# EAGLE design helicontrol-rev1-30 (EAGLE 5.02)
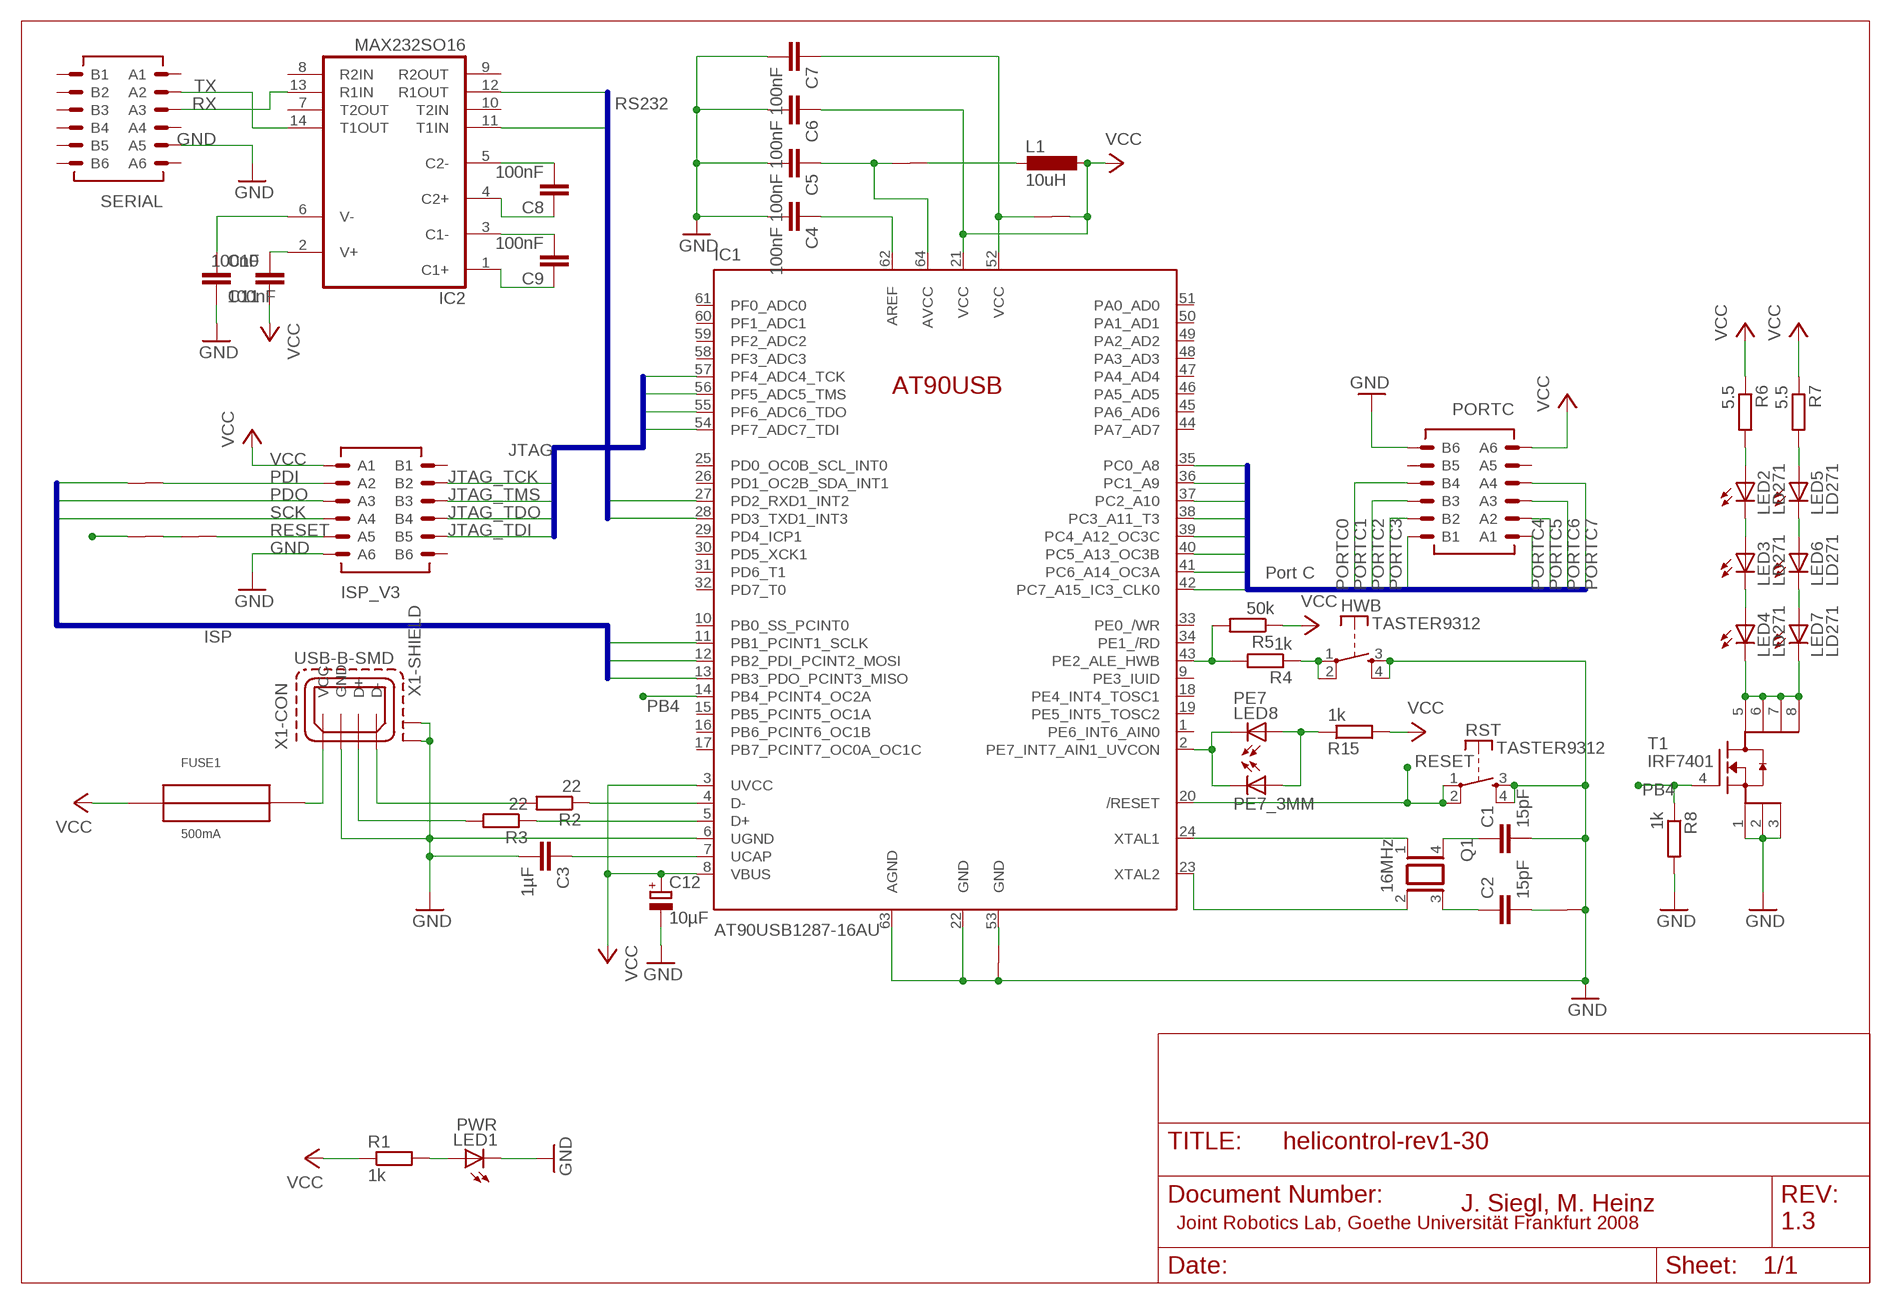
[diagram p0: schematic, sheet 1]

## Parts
C1  15pF  C-EUC1206  [C1206]
C2  15pF  C-EUC1206  [C1206]
C3  1µF  C-EUC1206  [C1206]
C4  100nF  C-EUC1206  [C1206]
C5  100nF  C-EUC1206  [C1206]
C6  100nF  C-EUC1206  [C1206]
C7  100nF  C-EUC1206  [C1206]
C8  100nF  C-EUC1206  [C1206]
C9  100nF  C-EUC1206  [C1206]
C10  100nF  C-EUC1206  [C1206]
C11  100nF  C-EUC1206  [C1206]
C12  10µF  CPOL-EUUD-5X5,8  [UD-5X5,8_NICHICON]
FUSE1  500mA  SMD-FUSE  [SMD-FUSE]
HWB  TASTER9312  [TASTER9312]
IC1  AT90USB1287-16AU  AT90USB-TQFP  [TQFP64]
IC2  MAX232SO16  [SO16]
ISP_V3  ML12G  [ML12G]
J0  R01206W  [R1206W]
J1  R01206W  [R1206W]
J2  R01206W  [R1206W]
J3  R01206W  [R1206W]
J4  R01206W  [R1206W]
J5  R01206W  [R1206W]
J6  R01206W  [R1206W]
L1  10uH  L-EUL2012C  [L2012C]
LED1  PWR  LEDCHIPLED_1206  [CHIPLED_1206]
LED2  LD271  LED5MM  [LED5MM]
LED3  LD271  LED5MM  [LED5MM]
LED4  LD271  LED5MM  [LED5MM]
LED5  LD271  LED5MM  [LED5MM]
LED6  LD271  LED5MM  [LED5MM]
LED7  LD271  LED5MM  [LED5MM]
LED8  PE7  LEDCHIPLED_1206  [CHIPLED_1206]
PE7_3MM  LED3MM  [LED3MM]
PORTC  ML12G  [ML12G]
Q1  16MHz  XTAL4-SMD  [XTAL4]
R1  1k  R-EU_R1206W  [R1206W]
R2  22  R-EU_R1206W  [R1206W]
R3  22  R-EU_R1206W  [R1206W]
R4  1k  R-EU_R1206W  [R1206W]
R5  50k  R-EU_R1206W  [R1206W]
R6  5.5  R-EU_R1206W  [R1206W]
R7  5.5  R-EU_R1206W  [R1206W]
R8  1k  R-EU_R1206W  [R1206W]
R15  1k  R-EU_R1206W  [R1206W]
RST  TASTER9312  [TASTER9312]
SERIAL  ML12G  [ML12G]
T1  IRF7401  [SO8]
X1  USB-B-SMD  [USB-B-SMD]

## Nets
D+: R3.2 X1.D+(-CON:D+)
D-: R2.2 X1.D-(-CON:D-)
GND: C1.2 C2.2 C3.2 C4.2 C5.2 C6.2 C7.2 C10.2 C12.- HWB.3(S) HWB.4(S) IC1.6(UGND) IC1.22(GND) IC1.53(GND) IC1.63(AGND) ISP_V3.A6 J0.1 J0.2 J1.1 J1.2 LED1.C PORTC.B6 R8.2 RST.3(S) RST.4(S) SERIAL.A5 T1.1(S) T1.2(S) T1.3(S) X1.GND(-CON:GND) X1.M1(-SHIELD:S1) X1.M2(-SHIELD:S2)
JTAG_TCK: IC1.57(PF4_ADC4_TCK) ISP_V3.B2
JTAG_TDI: IC1.54(PF7_ADC7_TDI) ISP_V3.B5
JTAG_TDO: IC1.55(PF6_ADC6_TDO) ISP_V3.B4
JTAG_TMS: IC1.56(PF5_ADC5_TMS) ISP_V3.B3
N$1: FUSE1.P$2 X1.VCC(-CON:VCC)
N$2: LED1.A R1.2
N$3: IC1.23(XTAL2) Q1.2
N$4: IC1.24(XTAL1) Q1.1
N$5: IC1.43(PE2_ALE_HWB) R4.2 R5.2
N$6: C4.1 IC1.62(AREF)
N$9: IC1.4(D-) R2.1
N$10: IC1.5(D+) R3.1
N$11: LED2.A R6.2
N$12: C5.1 IC1.64(AVCC) J2.1 J2.2 L1.2
N$13: C3.1 IC1.7(UCAP)
N$14: LED2.K(C) LED3.A
N$15: HWB.1(P) HWB.2(P) R4.1
N$16: LED3.K(C) LED4.A
N$17: C8.1 IC2.4(C2+)
N$18: C8.2 IC2.5(C2-)
N$19: C9.2 IC2.3(C1-)
N$20: C9.1 IC2.1(C1+)
N$21: C10.1 IC2.6(V-)
N$22: C11.2 IC2.2(V+)
N$23: C1.1 Q1.4
N$24: C2.1 Q1.3
N$25: LED4.K(C) LED7.K(C) T1.5(D) T1.6(D) T1.7(D) T1.8(D)
N$26: J4.1 J5.2
N$27: LED6.K(C) LED7.A
N$28: LED5.K(C) LED6.A
N$29: LED5.A R7.2
N$31: ISP_V3.A5 J5.1
N$32: ISP_V3.A2 J6.1
N$35: IC1.2(PE7_INT7_AIN1_UVCON) LED8.C PE7_3MM.K(C)
N$36: LED8.A PE7_3MM.A R15.1
PB4: IC1.14(PB4_PCINT4_OC2A) R8.1 T1.4(G)
PDI: IC1.12(PB2_PDI_PCINT2_MOSI) J6.2
PDO: IC1.13(PB3_PDO_PCINT3_MISO) ISP_V3.A3
PORTC0: IC1.35(PC0_A8) PORTC.B4
PORTC1: IC1.36(PC1_A9) PORTC.B3
PORTC2: IC1.37(PC2_A10) PORTC.B2
PORTC3: IC1.38(PC3_A11_T3) PORTC.B1
PORTC4: IC1.39(PC4_A12_OC3C) PORTC.A1
PORTC5: IC1.40(PC5_A13_OC3B) PORTC.A2
PORTC6: IC1.41(PC6_A14_OC3A) PORTC.A3
PORTC7: IC1.42(PC7_A15_IC3_CLK0) PORTC.A4
RESET: IC1.20(/RESET) J4.2 RST.1(P) RST.2(P)
RX: IC2.13(R1IN) SERIAL.A3
RXOUT: IC1.27(PD2_RXD1_INT2) IC2.12(R1OUT)
SCK: IC1.11(PB1_PCINT1_SCLK) ISP_V3.A4
TX: IC2.14(T1OUT) SERIAL.A2
TXIN: IC1.28(PD3_TXD1_INT3) IC2.11(T1IN)
VCC: C6.1 C7.1 C11.1 C12.+ FUSE1.P$1 IC1.3(UVCC) IC1.8(VBUS) IC1.21(VCC) IC1.52(VCC) ISP_V3.A1 J3.1 J3.2 L1.1 PORTC.A6 R1.1 R5.1 R6.1 R7.1 R15.2
Unconnected: IC1.1(PE6_INT6_AIN0) IC1.9(PE3_IUID) IC1.10(PB0_SS_PCINT0) IC1.15(PB5_PCINT5_OC1A) IC1.16(PB6_PCINT6_OC1B) IC1.17(PB7_PCINT7_OC0A_OC1C) IC1.18(PE4_INT4_TOSC1) IC1.19(PE5_INT5_TOSC2) IC1.25(PD0_OC0B_SCL_INT0) IC1.26(PD1_OC2B_SDA_INT1) IC1.29(PD4_ICP1) IC1.30(PD5_XCK1) IC1.31(PD6_T1) IC1.32(PD7_T0) IC1.33(PE0_/WR) IC1.34(PE1_/RD) IC1.44(PA7_AD7) IC1.45(PA6_AD6) IC1.46(PA5_AD5) IC1.47(PA4_AD4) IC1.48(PA3_AD3) IC1.49(PA2_AD2) IC1.50(PA1_AD1) IC1.51(PA0_AD0) IC1.58(PF3_ADC3) IC1.59(PF2_ADC2) IC1.60(PF1_ADC1) IC1.61(PF0_ADC0) IC2.7(T2OUT) IC2.8(R2IN) IC2.9(R2OUT) IC2.10(T2IN) ISP_V3.B1 ISP_V3.B6 PORTC.A5 PORTC.B5 SERIAL.A1 SERIAL.A4 SERIAL.A6 SERIAL.B1 SERIAL.B2 SERIAL.B3 SERIAL.B4 SERIAL.B5 SERIAL.B6

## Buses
PDI,PDO,SCK
RXOUT,TXIN
JTAG_TCK,JTAG_TMS,JTAG_TDO,JTAG_TDI
PORTC[0..7]

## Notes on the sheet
- RS232
- JTAG
- Port C
- ISP
- J. Siegl, M. Heinz
- Joint Robotics Lab, Goethe Universität Frankfurt 2008 | 1.3

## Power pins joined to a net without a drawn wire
GND: IC2.15(GND)
VCC: IC2.16(VCC)

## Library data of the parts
C1-C11 = resistor:C-EU: CAPACITOR, European symbol
C12 = rcl:CPOL-EU: POLARIZED CAPACITOR, European symbol
FUSE1 = cvg-smd:SMD-FUSE: SMD-FUSE
HWB RST = cvg-smd:TASTER9312: TASTER 9312 SWITCH Von Reichelt Elektronik
IC1 = controller-micro_atmel_jd:AT90USB
IC2 = cvg-smd:MAX232: RS232 TRANSEIVER
ISP_V3 PORTC SERIAL = cvg-con-erni:ML12G: Male SMC Connector vertical, type Q, low profile
J0 J1-J6 = cvg-smd:R0: Zero Ohm Resistor
L1 = rcl:L-EU: INDUCTOR, European symbol
LED1-LED8 PE7_3MM = led:LED: LED
Q1 = cvg-smd:XTAL4-SMD: xtal
R1-R8 R15 = rcl:R-EU_: RESISTOR, European symbol
T1 = cvg-smd:IRF7401: IRF 7401 n-Channel Hexfet Power Mosfet SO-8
X1 = joergsmikrocontroller-net-usb:USB-B-SMD

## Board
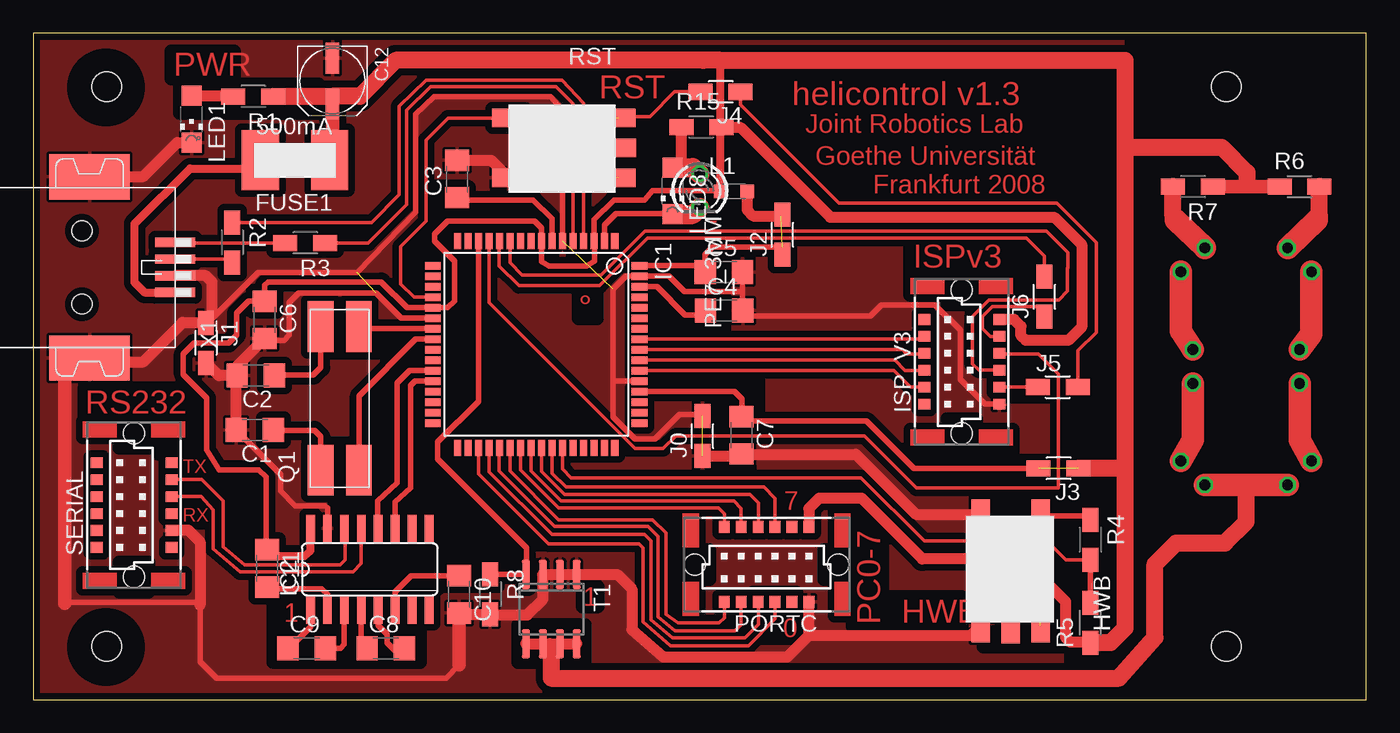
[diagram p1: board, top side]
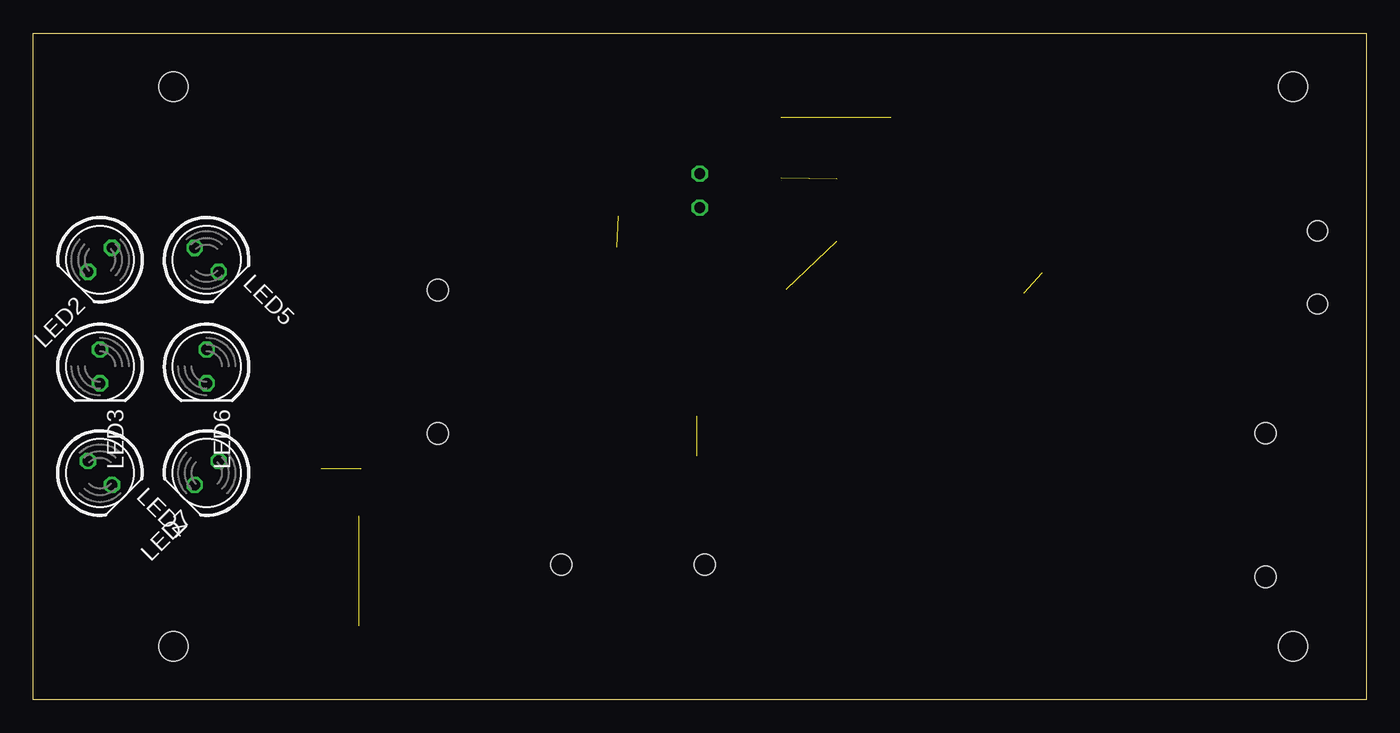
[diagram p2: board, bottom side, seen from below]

Size 100 x 50 mm. Coordinates in mm from the lower left corner, seen from the top.
Outline: 0,50 0,0 100,0 100,50 0,50
Copper layers (1*16): Top 0.035mm / dielectric 1.5mm / Bottom 0.035mm
Design rules "PCB-POOL *": minimum track width 6mil, minimum drill 12mil, track to track 6mil, track to pad 6mil, pad to pad 6mil, via to via 6mil, smd to smd 6mil, copper to edge 20mil, drill to drill 8mil, minimum pad ring 8mil, minimum via ring 6mil, stop-mask expansion 3mil, vias tented up to drill 0mil, thermal gap 8mil
Holes 2.2 mm at 5.5,46 5.5,4 89.5,46 89.5,4
tRestrict: area 3.2,43.8 to 7.7,48.2; area 87.3,1.7 to 91.7,6.1; area 87.2,43.8 to 91.7,48.2; area 3.2,1.8 to 7.7,6.2; area 82.6,49.1 to 83,49.5; area 18,2.8 to 29,7.2; area 29.8,8.1 to 30.6,8.8; area 8.2,31.4 to 9,32.9; area 10.3,46.6 to 15.1,48.6; area 15.4,44.5 to 20.1,46; area 44.2,38 to 47.2,43.4; area 29.8,36.6 to 32.5,38.5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

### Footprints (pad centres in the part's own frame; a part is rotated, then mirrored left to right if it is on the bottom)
C1206 = smd 1.6 x 1.8: 1 -1.4,0; 2 1.4,0
UD-5X5,8_NICHICON = smd 2.3 x 1: + 1.725,0; - -1.7,0
SMD-FUSE = smd 2.794 x 4.5: P$1 -2.591,0; P$2 2.591,0
TASTER9312 = smd 2.5 x 1.4: 1 -7,2.5; 2 1.25,2.5; 3 -7,-2; 4 1.25,-2 | smd 3 x 1.4: 5 1.05,0.25
TQFP64 = smd 1.194 x 0.559: 1 -7.76,5.905; 2 -7.76,5.118; 3 -7.76,4.331; 4 -7.76,3.543; 5 -7.76,2.756; 6 -7.76,1.968; 7 -7.76,1.181; 8 -7.76,0.394; 9 -7.76,-0.394; 10 -7.76,-1.181; 11 -7.76,-1.968; 12 -7.76,-2.756; 13 -7.76,-3.543; 14 -7.76,-4.331; 15 -7.76,-5.118; 16 -7.76,-5.905; 33 7.76,-5.905; 34 7.76,-5.118; 35 7.76,-4.331; 36 7.76,-3.543; 37 7.76,-2.756; 38 7.76,-1.968; 39 7.76,-1.181; 40 7.76,-0.394; 41 7.76,0.394; 42 7.76,1.181; 43 7.76,1.968; 44 7.76,2.756; 45 7.76,3.543; 46 7.76,4.331; 47 7.76,5.118; 48 7.76,5.905 | smd 0.559 x 1.194: 17 -5.905,-7.76; 18 -5.118,-7.76; 19 -4.331,-7.76; 20 -3.543,-7.76; 21 -2.756,-7.76; 22 -1.968,-7.76; 23 -1.181,-7.76; 24 -0.394,-7.76; 25 0.394,-7.76; 26 1.181,-7.76; 27 1.968,-7.76; 28 2.756,-7.76; 29 3.543,-7.76; 30 4.331,-7.76; 31 5.118,-7.76; 32 5.905,-7.76; 49 5.905,7.76; 50 5.118,7.76; 51 4.331,7.76; 52 3.543,7.76; 53 2.756,7.76; 54 1.968,7.76; 55 1.181,7.76; 56 0.394,7.76; 57 -0.394,7.76; 58 -1.181,7.76; 59 -1.968,7.76; 60 -2.756,7.76; 61 -3.543,7.76; 62 -4.331,7.76; 63 -5.118,7.76; 64 -5.905,7.76
SO16 = smd 0.66 x 2.032: 1 -4.445,-3.073; 2 -3.175,-3.073; 3 -1.905,-3.073; 4 -0.635,-3.073; 5 0.635,-3.073; 6 1.905,-3.073; 7 3.175,-3.073; 8 4.445,-3.073; 9 4.445,3.073; 10 3.175,3.073; 11 1.905,3.073; 12 0.635,3.073; 13 -0.635,3.073; 14 -1.905,3.073; 15 -3.175,3.073; 16 -4.445,3.073
ML12G = smd 0.8 x 0.9: A1 3.175,-2.806; A2 1.905,-2.806; A3 0.635,-2.806; A4 -0.635,-2.806; A5 -1.905,-2.806; A6 -3.175,-2.806; B1 3.175,2.806; B2 1.905,2.806; B3 0.635,2.806; B4 -0.635,2.806; B5 -1.905,2.806; B6 -3.175,2.806 | hole 1.6: 5.385,0; -5.385,0
R1206W = smd 1.8 x 1.2: 1 -1.499,0; 2 1.499,0
L2012C = smd 1 x 1: 1 -1,0; 2 1,0
CHIPLED_1206 = smd 1.5 x 1.5: A 0,-1.75; C 0,1.75
LED5MM = drill 0.813 octagon: A -1.27,0; K 1.27,0
LED3MM = drill 0.813 octagon: A -1.27,0; K 1.27,0
XTAL4 = smd 3.81 x 1.93: 1 -5.397,-1.27; 2 5.397,-1.27; 3 5.397,1.587; 4 -5.397,1.587
SO8 = smd 0.6 x 2.2: 1 -1.905,-2.6; 2 -0.635,-2.6; 3 0.635,-2.6; 4 1.905,-2.6; 5 1.905,2.6; 6 0.635,2.6; 7 -0.635,2.6; 8 -1.905,2.6
USB-B-SMD = smd 3 x 0.7: D+ 7,1.875; D- 7,0.625; GND 7,-0.625; VCC 7,-1.875 | smd 6.04 x 3.4: M1 0.58,-6.8; M2 0.58,6.8 | hole 1.5: 0,-2.75; 0,2.75

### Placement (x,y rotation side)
C1  16.62,20.21 180 top
C2  16.7,24.31 180 top
C3  31.81,39.06 90 top
C4  51.83,29.2 0 top
C5  51.81,32.1 0 top
C6  17.35,28.5 270 top
C7  53.14,19.83 270 top
C8  26.45,3.85 0 top
C9  20.5,3.85 0 top
C10  31.95,7.89 270 top
C11  17.55,9.85 270 top
C12  22.44,46.44 270 top
FUSE1  19.63,40.47 180 top
HWB  73.07,6.79 270 top
IC1  37.74,26.65 270 top
IC2  25.24,9.78 0 top
ISP_V3  69.66,25.35 90 top
J0  50.21,19.79 90 top
J1  12.95,26.77 270 top
J2  56.2,34.9 90 top
J3  76.92,17.35 180 top
J4  51.57,45.6 180 top
J5  76.88,23.45 0 top
J6  75.85,30.23 90 top
L1  52.57,38.15 0 top
LED1  11.87,43.56 180 top
LED2  95,33 225 bottom
LED3  95,25 270 bottom
LED4  95,17 315 bottom
LED5  87,33 315 bottom
LED6  87,25 270 bottom
LED7  87,17 225 bottom
LED8  47.95,38.18 180 top
PE7_3MM  50,38.19 270 top
PORTC  55.01,10.13 180 top
Q1  23.15,22.6 90 top
R1  16.5,45.26 180 top
R2  14.94,34.31 270 top
R3  20.41,34.27 180 top
R4  79.31,12 270 top
R5  79.31,5.77 90 top
R6  95,38.5 0 top
R7  87,38.5 180 top
R8  34.28,7.89 270 top
R15  50.12,42.97 0 top
RST  42.67,41.16 0 top
SERIAL  7.56,14.6 90 top
T1  38.87,6.78 180 top
X1  3.65,32.43 0 top

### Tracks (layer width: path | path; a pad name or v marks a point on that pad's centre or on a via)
D+
  Top 0.254: X1.D+ 11.1,34.3 11.15,34.25 11.17,34.27 R3.2
D-
  Top 0.254: 14.94,32.71 15,32.65 | R2.2 14.94,32.71 | X1.D- 14.6,33.05 14.94,32.71
GND  (4 unrouted)
  Top 0.406: HWB.3 71.07,13.69 | C3.2 | ISP_V3.A6 71.39,22.17 69.55,24.01 69.55,27.71 67.65,29.61 63.65,29.61 62.8,28.76 53.1,28.76 53.14,28.8 C4.2 53.23,28.7 53.21,28.67 | 53.21,31.75 53.2,31.76 | IC1.63 47.7,31.76 48.85,30.61 52.95,30.61 53.2,30.56 53.21,30.56 | 53.21,31.75 C5.2 | 53.21,30.56 53.21,31.75 | 53.21,30.56 53.21,28.67 | 53.21,28.67 53.2,28.66 | IC1.63 | 39.7,39.1 39.7,44.24 38.8,45.25 30.08,45.25 28.7,43.91 28.7,36.56 24.28,32.05 16.85,32.05 13,28.2 12.95,28.25 J1.1 | 39.7,39.1 IC1.6 | RST.3 39.65,39.16 39.7,39.1 | 43.5,23.9 43.5,21.2 45.15,19.55 46.65,19.55 48.49,21.39 50.21,21.39 J0.2 | IC1.53 43.5,23.9 | IC1.22 27.58,28.62 25.7,30.5 19.9,30.5 19.2,29.8 19.2,27.35 18.8,26.95 17.5,26.95 C6.2 | IC2.15 22.07,14.38 21.9,14.55 19.65,14.55 18.55,15.65 18.55,16.88 C1.2 | 43.5,23.9 43.5,30.82 44.45,31.77 IC1.63 | 31.95,2.6 30.95,1.6 13.75,1.6 12.5,2.85 12.5,7.1 | 12.5,11.85 12.4,11.75 12.4,7.2 12.3,7.3 2.35,7.3
  Top 0.813: 71.05,5.66 71.07,5.63 HWB.4 | HWB.4 71,5.61 | X1.M1 4.25,25.6 | 10.3,12.68 10.31,12.69 SERIAL.A5 10.37,12.7 11.65,12.7 12.5,11.85 12.5,7.1 | 58.19,4.81 PORTC.B6 | HWB.4 70.94,5.4 | C7.2 53.1,18.39 | C3.2 34.37,40.45 RST.3 | 58.19,4.81 70.35,4.81 HWB.4 | 58.19,4.81 56.58,3.2 47.25,3.2 44.9,5.25 44.9,8.3 43.82,9.38 T1.1 T1.2 T1.3 38.23,7.53 37.05,6.35 34.33,6.35 R8.2 32.05,6.39 C10.2 | 71.07,14.08 HWB.3 70.96,13.9 66.2,13.9 61.7,18.4 53.17,18.4 C7.2 | C1.2 15.22,24.23 C2.2 | C2.2 13.91,24.31 J1.2 | C2.2 15.3,25.05 C6.2 | J0.1 53.14,18.29 C7.2 | 4.25,39.25 X1.M2 | X1.M1 4.27,25.63 4.3,25.6 | 3.89,25.35 8.25,25.35 11.2,28.3 12.9,28.3 12.93,28.27 J1.1 12.95,28.5 13.4,28.95 13.4,31.35 12.95,31.8 X1.GND | 5,39.25 5,39.3 5.05,39.25 8.25,39.25 10.81,41.81 LED1.C | X1.M1 4.25,25.65 | X1.M1 | 2.75,25.63 X1.M1
  Top 1.016: 31.95,2.6 C10.2 | 2.35,7.2 2.35,7.3 2.35,24.45 2.35,25.63 2.75,25.63
  Top 1.27: 6,39.25 5,39.25 4.25,39.25 | X1.M1 4.3,25.63 4.3,25.5 5.2,25.5 | 5.2,25.5 6,25.5 | 5.2,25.5 5.2,25.65 3.95,25.35
  Top 1.93: 3.95,25.35 3.89,25.35 3.89,25.85
  pour Top (isolate 0.5): -2,52 -2,-2 102,-2 102,52
JTAG_TCK
  Top 0.254: IC1.57 66.65,27.05 ISP_V3.B2
  Top 0.406: 66.81,27.21 ISP_V3.B2 66.86,27.22 66.85,27.21 66.75,27.31
JTAG_TDI
  Top 0.254: IC1.54 64.56,24.68 65.8,23.45 ISP_V3.B5
  Top 0.406: 66.83,23.41 ISP_V3.B5 66.86,23.32 66.85,23.31 66.75,23.41
JTAG_TDO
  Top 0.254: IC1.55 64.63,25.47 65.4,24.7 66.84,24.7 ISP_V3.B4
  Top 0.406: ISP_V3.B4 66.86,24.62 66.75,24.51 66.55,24.71
JTAG_TMS
  Top 0.254: IC1.56 65.19,26.26 65.5,25.95 66.82,25.95 ISP_V3.B3
  Top 0.406: 66.83,26.01 ISP_V3.B3 66.86,25.92 66.85,25.91 66.75,26.01
N$1
  Top 0.61: X1.VCC 8.35,30.55 7.6,31.3 7.6,35.7 11.75,39.85 16.75,39.85 16.8,39.8 16.82,39.82 FUSE1.P$2
N$2
  Top 0.406: R1.2 15,45.23 | R1.2 | 14.99,45.31 15,45.31 R1.2
  Top 0.813: LED1.A 14.99,45.31
N$3
  Top 0.406: IC1.23 24.58,27.83 Q1.2
N$4
  Top 0.406: IC1.24 28.7,27.05 24.45,22.8 24.45,17.24 Q1.1
N$5
  Top 0.254: IC1.43 39.7,17.3 40.35,16.65 62.1,16.65 66.85,11.9 76.05,11.9 77.45,10.5 R4.2 79.26,10.55
  Top 0.406: R5.2 79.31,7.3 79.2,7.41 79.31,7.53 R4.2
N$6
  Top 0.406: IC1.62 46.78,30.98 48.9,28.86 50.5,28.86 50.44,28.8 C4.1
N$9
  Top 0.254: R2.1 25.36,35.8 27.45,37.9 27.45,44.55 29.45,46.5 39.65,46.5 41.28,44.77 IC1.4
  Top 0.406: IC1.4 41.29,34.43
N$10
  Top 0.254: IC1.5 40.49,44.71 39.2,46 29.8,46 28,44.25 28,37.15 25.1,34.25 21.95,34.25 21.91,34.2 | 21.91,34.2 21.85,34.15 | R3.1 21.91,34.2
N$11
  Top 1.27: R6.2 96.5,36.3 96.3,36
  Top 1.676: LED2.A 96.3,36
N$12  (1 unrouted)
  Top 0.406: IC1.64 49.95,32.56 C5.1 50.41,33.41 50.95,33.95 56.2,33.95 J2.1
  Top 0.813: L1.2 53.57,36.73 54,36.3 56.1,36.3 J2.2
N$13
  Top 0.406: IC1.7 38.92,36.08 37.5,37.5 31.97,37.5 C3.1
N$14
  Top 1.676: LED2.K 95.9,27.42 LED3.A
N$15  (1 unrouted)
  Top 0.406: HWB.1 79.02,13.79 R4.1
N$16
  Top 1.676: LED3.K 95,19.5 LED4.A
N$17
  Top 0.406: IC2.4 24.61,4.29 C8.1
N$18
  Top 0.406: IC2.5 25.88,5.57 26.55,4.9 26.55,4.25 27.2,3.6 28.09,3.6 C8.2
N$19
  Top 0.406: IC2.3 23.34,4.14 23.05,3.85 C9.2
N$20
  Top 0.406: C9.1 19.2,3.85 20.8,5.45 IC2.1
N$21
  Top 0.406: IC2.6 27.15,8.1 28.35,9.3 C10.1
N$22
  Top 0.406: IC2.2 22.07,7.89 21.65,8.31 17.94,8.31 C11.2
N$23
  Top 0.406: Q1.4 21.56,19.74 21.1,20.2 C1.1
N$24
  Top 0.406: Q1.3 21.56,24.91 21,24.35 18.13,24.35 C2.1
N$25
  Top 0.406: LED7.K
  Top 0.813: T1.8 T1.7 38.75,4.18 | T1.5 T1.6 38.75,4.18 | 38.75,4.18 38.85,3.93
  Top 1.27: 38.85,3.93 38.85,1.6 81.45,1.6 84.15,4.65 84.15,10.15 85.75,11.75 89.4,11.75 91,13.35 91,16.1 | 91.15,16.1 91,15.95
  Top 1.676: LED7.K 91,16.1 91.15,16.1 LED4.K
N$26
  Top 0.254: J5.2 78.38,26.18 79.75,27.55 79.75,34.3 76.8,37.25 60.45,37.25 53.05,44.65 53.05,45.6 J4.1
N$27
  Top 1.676: LED6.K 87,19.5 LED7.A
N$28
  Top 1.676: LED5.K 86.1,27.67 LED6.A
N$29
  Top 1.27: R7.2 85.5,36.3 85.7,36
  Top 1.676: LED5.A 85.7,36
N$31
  Top 0.254: ISP_V3.A5 J5.1
N$32
  Top 0.254: ISP_V3.A2 71.8,27.25 71.2,27.85 71.2,28.75 71.95,29.5 75.85,29.5 J6.1
N$35
  Top 0.406: IC1.2 42.85,35.6 43.7,36.45 47.85,36.45 47.9,36.5 47.95,36.45 LED8.C
  Top 1.422: LED8.C 47.98,36.4 49.48,36.4 PE7_3MM.K
N$36
  Top 0.813: LED8.A 47.95,39.95 48.62,39.95 R15.1
  Top 1.422: PE7_3MM.A 50,39.4 49.47,39.93 LED8.A
PB4
  Top 0.406: T1.4 R8.1 | T1.4 36.95,9.39 | T1.4 37,9.42 37,11.4 30.35,18.05 30.35,19.31 33.41,22.37 IC1.14
PDI
  Top 0.254: IC1.12 34.95,34.38 34.95,32.55 36.44,31.06 42.5,31.06 46.08,34.65 74.5,34.65 75.85,33.3 J6.2
PDO
  Top 0.254: IC1.13 34.19,29.81 45.15,18.85 47.25,18.85 48.2,19.8 62.35,19.8 66.25,15.9 76.9,15.9 76.9,24.45 75.41,25.94 72.52,25.94 ISP_V3.A3
PORTC0
  Top 0.254: PORTC.B4 55.65,6.05 53.65,4.05 47.8,4.05 45.75,5.85 45.75,11.4 45.45,11.7 38.65,11.7 33.4,16.95 IC1.35
PORTC1
  Top 0.254: PORTC.B3 54.4,7.05 54.4,5.65 53.4,4.65 47.95,4.65 46.35,6 46.35,11.9 45.85,12.4 38.9,12.4 34.2,17.1 IC1.36
PORTC2
  Top 0.254: PORTC.B2 53.11,5.61 52.65,5.15 48.15,5.15 46.85,6.2 46.85,12.25 46.1,13 39.1,13 34.95,17.15 34.95,18.86 IC1.37
PORTC3
  Top 0.254: IC1.38 35.75,18.88 35.75,17.15 39.4,13.5 46.45,13.5 47.45,12.5 47.45,6.4 48.35,5.75 51.45,5.75 51.85,6.15 PORTC.B1
PORTC4
  Top 0.254: IC1.39 36.55,17.25 39.4,14.4 51.4,14.4 51.85,13.95 51.85,12.7 PORTC.A1
PORTC5
  Top 0.254: IC1.40 37.34,17.16 39.6,14.9 52.55,14.9 53.1,14.35 53.1,12.7 PORTC.A2
PORTC6
  Top 0.254: IC1.41 38.13,17.12 39.85,15.4 53.75,15.4 54.4,14.75 54.4,12.71 PORTC.A3
PORTC7
  Top 0.254: IC1.42 38.92,16.98 39.95,15.95 54.8,15.95 55.65,15.1 55.65,12.69 PORTC.A4
RESET  (1 unrouted)
  Top 0.254: IC1.20 28.55,30.2 27.55,31.2 27.55,34 29.45,35.9 29.45,42 31.1,43.65 RST.1 | 44.02,43.75 44.37,44.1 | RST.2 44.02,43.75 | 44.02,43.75 46.25,43.75 48.1,45.6 J4.2 50.1,45.6
RX
  Top 0.254: IC2.13 24.61,10.21 24,9.6 15.5,9.6 13.5,11.3 13.5,14.25 12.6,15.25 10.38,15.25 SERIAL.A3
RXOUT
  Top 0.406: IC1.27 28.22,24.68 27.3,23.76 27.3,16.26 25.85,14.91 25.85,12.63 IC2.12
SCK
  Top 0.254: ISP_V3.A4 70.94,24.71 70.45,25.2 70.45,28.75 71.7,30 76.93,30 77.6,30.66 77.6,32.4 77.6,33.55 76,35.15 45.88,35.15 42.6,31.86 36.69,31.86 35.75,32.8 35.75,34.4 IC1.11
TX
  Top 0.254: SERIAL.A2 12.65,16.5 14.25,14.9 14.25,11.45 15.85,10.1 23,10.1 23.4,10.5 23.4,12.79 IC2.14
TXIN
  Top 0.406: IC1.28 28.63,23.9 28.3,23.56 28.3,15.86 27.15,14.81 IC2.11
VCC  (1 unrouted)
  Top 0.254: 22.4,45.27 22.35,45.27 22.32,45.25 22.32,45.26 22.3,45.26 22.3,44.85 C12.+ 22.44,44.69 C12.+
  Top 0.406: 38.12,34.4 IC1.8 | IC1.8 38.1,34.41 38.12,34.4 | IC1.8 38.13,32.88 38.7,32.51 41.5,32.51 42.1,32.91 42.1,34.38 IC1.3 42.07,36.02 43.55,37.5 45.85,37.5 46.45,38.2 51.55,38.2 | 38.12,34.4 38.12,35.39 37.6,35.91 31.1,35.91 30.1,34.91 30.1,34.41 31.6,32.91 31.6,29.91 31.09,29.41 IC1.21 | IC1.21 29.93,29.36 | IC1.21 28.04,29.41 26.1,31.35 17.6,31.35 17.35,31.1 C6.1 | C6.1 | C6.1 16.15,29.9 15.25,29 15.25,27.35 14.65,26.75 12.05,26.75 11.25,25.95 11.25,24.4 13,22.65 13,18.75 13.95,17.25 16.9,17.25 17.45,16.7 17.45,11.38 C11.1 | C7.1 53.21,21.16 | C7.1 53.47,20.9 62.5,20.9 66.05,17.35 J3.2 | IC1.52 52.59,23.11 53.15,22.55 C7.1 | 51.57,37.98 51.6,37.95 | 51.57,37.98 L1.1 | 51.55,38 51.57,37.98 | FUSE1.P$1 22.22,41.92 | 22.5,42.02 22.5,41.9
  Top 0.61: IC2.16 20.8,11.16 20.35,10.76 17.55,10.76 17.55,11.2 17.55,11.28 C11.1 | 51.55,38 51.55,38.2 51.55,42.75 | 50.25,47.96 50.3,47.91 | 51.55,48 51.55,47.96 51.55,43.19 R15.2
  Top 0.813: R5.1 79.29,4.3 77.8,4.3 77.45,4.65 77.45,7.35 74.25,10.55 66.7,10.55 62.15,15.1 58.95,15.1 58.19,14.34 PORTC.A6 | ISP_V3.A1 73.58,28.52 74.1,28 74.1,27.3 74.45,26.95 77.65,26.95 78.65,27.95 78.65,34.15 76.6,36.2 59.8,36.2 53.05,42.95 51.75,42.95 | 17.55,11.28 C11.1 17.55,11.27 17.55,11.2 | 51.75,42.95 R15.2 | 51.55,38 51.55,38.03 L1.1 | 51.55,42.75 51.75,42.95 | 91.05,39 91,38.5 | 22.3,45.26 22.3,45.3 | C12.+ 22.45,44.63
  Top 1.016: R7.1 91,38.5 R6.1 | 22.5,41.83 22.52,41.83 22.44,41.91 C12.+
  Top 1.27: FUSE1.P$1 22.5,40.25 22.5,41.83 22.5,42.02 22.5,42.23 22.52,42.25 | R5.1 80.82,4.27 81.9,5.35 81.9,17.25 | J3.1 81.8,17.35 81.9,17.25 | 81.9,41.45 81.9,47.96 51.55,47.96 50.25,47.96 27.19,47.96 24.5,45.27 22.4,45.27 | 81.9,41.45 81.9,17.25 | 81.9,41.45 89.15,41.45 91.05,39.55 91.05,39 | 22.3,45.26 R1.1

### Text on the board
Top: PWR | RST | helicontrol v1.3 | Joint Robotics Lab | Goethe Universität | Frankfurt 2008 | - | ISPv3 | ° | RS232 | TX | 7 | RX | 1 | 1 | PC0-7 | HWB | 0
